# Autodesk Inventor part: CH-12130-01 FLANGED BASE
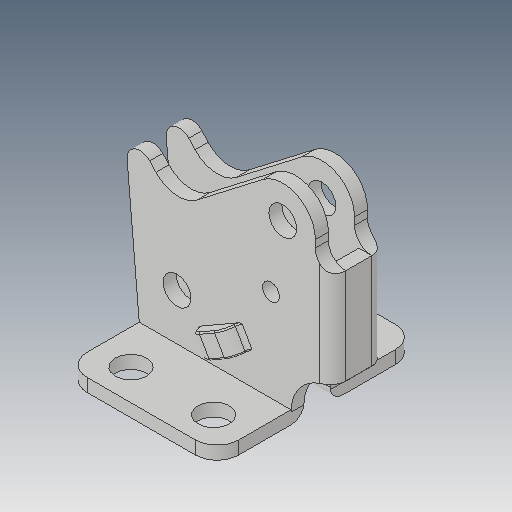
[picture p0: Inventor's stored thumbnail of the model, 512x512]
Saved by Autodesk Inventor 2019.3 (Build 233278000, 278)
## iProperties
Created: 2012-09
Part Number: CH-12130-01 FLANGED BASE
Material: Ogólny
Document SubType Name: Modeling
Designer: CADENGINEERING4
Density: 1 g/cm^3
Appearance: Domyślna
Author: CADENGINEERING4
Revision Number: ÈÎºÎ
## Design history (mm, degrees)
feature "Ô²½Ç11"
node "Bryła1"
